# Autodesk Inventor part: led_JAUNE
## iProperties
Created: 2011-01
Part Number: led_JAUNE
Document SubType Name: Modeling
Designer: eric
Density: 1 g/cm^3
Mass: 0.146477 g
Surface Area: 1.52371 cm^2
Volume: 0.146477 cm^3
Author: eric
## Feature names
1. Base1
